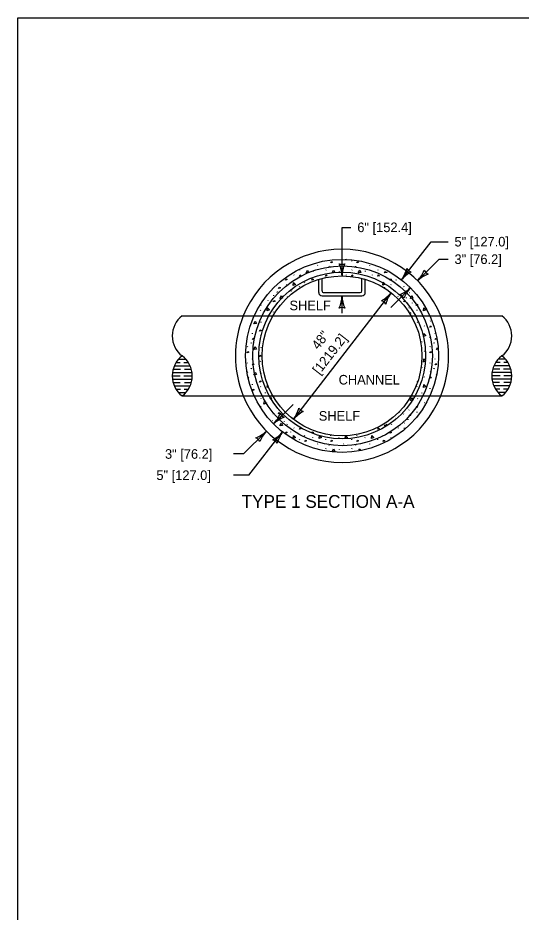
# Model space of a CAD drawing. Extents: x 49991.4 to 50028.3, y 49987.6 to 50011.4.
# Drawn here: x 49999.38 to 50002.53, y 49993.41 to 49999 of the extents above; entities that cross this region are included whole.
import ezdxf

# ---------------------------------------------------------------- set-up
doc = ezdxf.new("R2010")
doc.units = 0
for name, color, linetype in [('Level 1', 7, 'Continuous'), ('Level 2', 7, 'Continuous'), ('Level 3', 7, 'Continuous'), ('Level 4', 7, 'Continuous')]:
    doc.layers.add(name, color=color, linetype=linetype)

msp = doc.modelspace()

# ---------------------------------------------------------------- linework, layer by layer
at = {"layer": 'Level 1'}
for p, q in [((50001.3077, 49997.4809), (50001.308, 49997.4779)), ((50001.471, 49997.4809), (50001.4713, 49997.4779)), ((50001.1475, 49997.422), (50001.1488, 49997.425)), ((50001.2319, 49997.4143), (50001.2332, 49997.4173)), ((50001.2588, 49997.4506), (50001.2602, 49997.4536)), ((50001.3108, 49997.422), (50001.3121, 49997.425)), ((50001.3304, 49997.4467), (50001.3318, 49997.4447)), ((50001.3355, 49997.4459), (50001.3368, 49997.4439)), ((50001.3951, 49997.4143), (50001.3961, 49997.4165)), ((50001.474, 49997.422), (50001.4754, 49997.425)), ((50001.4937, 49997.4467), (50001.495, 49997.4447)), ((50001.4988, 49997.4459), (50001.5001, 49997.4439)), ((50001.5584, 49997.4143), (50001.5597, 49997.4173)), ((50001.5854, 49997.4506), (50001.5867, 49997.4536)), ((50001.6373, 49997.422), (50001.6386, 49997.425)), ((50001.1102, 49997.3931), (50001.1116, 49997.3911)), ((50001.1779, 49997.3434), (50001.1792, 49997.3464)), ((50001.266, 49997.282), (50001.266, 49997.3644)), ((50001.2735, 49997.3931), (50001.2748, 49997.3911)), ((50001.2868, 49997.2924), (50001.2868, 49997.3703)), ((50001.4368, 49997.3931), (50001.4381, 49997.3911)), ((50001.5368, 49997.2924), (50001.5368, 49997.3703)), ((50001.5576, 49997.282), (50001.5576, 49997.3644)), ((50001.6, 49997.3931), (50001.6014, 49997.3911)), ((50001.6677, 49997.3434), (50001.669, 49997.3464)), ((50001.7505, 49997.3597), (50001.7518, 49997.3627)), ((50001.0653, 49997.3298), (50001.0666, 49997.3328)), ((50001.0956, 49997.2911), (50001.0969, 49997.2941)), ((50001.1444, 49997.3214), (50001.1448, 49997.3184)), ((50001.7183, 49997.3298), (50001.7197, 49997.3328)), ((50001.7975, 49997.3214), (50001.7978, 49997.3184)), ((50000.947, 49997.2336), (50000.9483, 49997.2316)), ((50000.9842, 49997.2625), (50000.9856, 49997.2655)), ((50001.0039, 49997.2873), (50001.0052, 49997.2853)), ((50001.009, 49997.2865), (50001.0103, 49997.2845)), ((50001.0686, 49997.2549), (50001.0699, 49997.2579)), ((50001.2868, 49997.2611), (50001.5368, 49997.2611)), ((50001.2972, 49997.282), (50001.5264, 49997.282)), ((50001.7628, 49997.2567), (50001.7637, 49997.2587)), ((50001.8146, 49997.2474), (50001.8159, 49997.2504)), ((50001.835, 49997.2835), (50001.8364, 49997.2815)), ((50001.831, 49997.184), (50001.8323, 49997.187)), ((50001.8501, 49997.2169), (50001.8514, 49997.2149)), ((50000.4118, 49997.1361), (50000.8623, 49997.1361)), ((50000.902, 49997.1703), (50000.9034, 49997.1733)), ((50000.9323, 49997.1317), (50000.9336, 49997.1347)), ((50000.9788, 49997.1361), (50001.8449, 49997.1361)), ((50000.9812, 49997.1619), (50000.9815, 49997.1589)), ((50001.8816, 49997.1703), (50001.8829, 49997.1733)), ((50001.9119, 49997.1317), (50001.9132, 49997.1347)), ((50001.9613, 49997.1361), (50002.4118, 49997.1361)), ((50000.9054, 49997.0955), (50000.9067, 49997.0985)), ((50000.947, 49997.0741), (50000.9483, 49997.0721)), ((50001.8849, 49997.0955), (50001.8863, 49997.0985)), ((50001.9266, 49997.0741), (50001.9279, 49997.0721)), ((50001.9638, 49997.1031), (50001.9652, 49997.1061)), ((50000.8514, 49997.0245), (50000.8527, 49997.0275)), ((50000.902, 49997.0109), (50000.9034, 49997.0139)), ((50001.9942, 49997.0245), (50001.9948, 49997.0257)), ((50000.8406, 49996.9683), (50000.842, 49996.9663)), ((50000.8457, 49996.9676), (50000.847, 49996.9656)), ((50001.9119, 49996.9722), (50001.9132, 49996.9752)), ((50001.9608, 49997.0025), (50001.9611, 49996.9995)), ((50001.9835, 49996.9683), (50001.9848, 49996.9663)), ((50001.9886, 49996.9676), (50001.9899, 49996.9656)), ((50000.821, 49996.9437), (50000.8223, 49996.9467)), ((50000.9054, 49996.936), (50000.9067, 49996.939)), ((50001.9266, 49996.9147), (50001.9279, 49996.9127)), ((50001.9638, 49996.9437), (50001.9652, 49996.9467)), ((50000.3734, 49996.8445), (50000.3995, 49996.8445)), ((50000.3891, 49996.8653), (50000.4345, 49996.8653)), ((50000.4219, 49996.8445), (50000.4502, 49996.8445)), ((50000.8179, 49996.8431), (50000.8182, 49996.8401)), ((50000.8514, 49996.8651), (50000.8527, 49996.8681)), ((50000.902, 49996.8514), (50000.9034, 49996.8544)), ((50001.9608, 49996.8431), (50001.9611, 49996.8401)), ((50001.9942, 49996.8651), (50001.9956, 49996.8681)), ((50002.4017, 49996.8445), (50002.3734, 49996.8445)), ((50002.4346, 49996.8653), (50002.3891, 49996.8653)), ((50002.4502, 49996.8445), (50002.4241, 49996.8445)), ((50000.355, 49996.8028), (50000.4006, 49996.8028)), ((50000.3624, 49996.8236), (50000.4612, 49996.8236)), ((50000.4252, 49996.8028), (50000.4686, 49996.8028)), ((50000.821, 49996.7842), (50000.8223, 49996.7872)), ((50000.8406, 49996.8089), (50000.842, 49996.8069)), ((50000.8457, 49996.8081), (50000.847, 49996.8061)), ((50001.9119, 49996.8128), (50001.9132, 49996.8158)), ((50001.9638, 49996.7842), (50001.9652, 49996.7872)), ((50001.9835, 49996.8089), (50001.9848, 49996.8069)), ((50001.9886, 49996.8081), (50001.9899, 49996.8061)), ((50002.3985, 49996.8028), (50002.355, 49996.8028)), ((50002.4613, 49996.8236), (50002.3624, 49996.8236)), ((50002.4687, 49996.8028), (50002.423, 49996.8028)), ((50000.3493, 49996.7611), (50000.3984, 49996.7611)), ((50000.3507, 49996.7819), (50000.4729, 49996.7819)), ((50000.3507, 49996.7403), (50000.4729, 49996.7403)), ((50000.423, 49996.7611), (50000.4743, 49996.7611)), ((50000.9054, 49996.7765), (50000.9067, 49996.7795)), ((50001.9266, 49996.7552), (50001.9279, 49996.7532)), ((50002.4006, 49996.7611), (50002.3494, 49996.7611)), ((50002.473, 49996.7819), (50002.3508, 49996.7819)), ((50002.473, 49996.7403), (50002.3508, 49996.7403)), ((50002.4744, 49996.7611), (50002.4252, 49996.7611)), ((50000.355, 49996.7195), (50000.3995, 49996.7195)), ((50000.3624, 49996.6986), (50000.4612, 49996.6986)), ((50000.3734, 49996.6778), (50000.4016, 49996.6778)), ((50000.424, 49996.6778), (50000.4502, 49996.6778)), ((50000.4262, 49996.7195), (50000.4686, 49996.7195)), ((50000.8514, 49996.7056), (50000.8527, 49996.7086)), ((50000.902, 49996.6919), (50000.9034, 49996.6949)), ((50001.8816, 49996.6919), (50001.8829, 49996.6949)), ((50001.9608, 49996.6836), (50001.9611, 49996.6806)), ((50002.3974, 49996.7195), (50002.355, 49996.7195)), ((50002.4613, 49996.6986), (50002.3624, 49996.6986)), ((50002.3996, 49996.6778), (50002.3734, 49996.6778)), ((50002.4502, 49996.6778), (50002.422, 49996.6778)), ((50002.4687, 49996.7195), (50002.4241, 49996.7195)), ((50000.3891, 49996.6569), (50000.4345, 49996.6569)), ((50000.4118, 49996.6361), (50000.8624, 49996.6361)), ((50000.9054, 49996.6171), (50000.9067, 49996.6201)), ((50000.9323, 49996.6533), (50000.9336, 49996.6563)), ((50000.9789, 49996.6361), (50001.8448, 49996.6361)), ((50001.8849, 49996.6171), (50001.8863, 49996.6201)), ((50001.9119, 49996.6533), (50001.9132, 49996.6563)), ((50001.9613, 49996.6361), (50002.4118, 49996.6361)), ((50002.4346, 49996.6569), (50002.3891, 49996.6569)), ((50000.947, 49996.5958), (50000.9483, 49996.5938)), ((50001.0092, 49996.5899), (50001.0101, 49996.5886)), ((50001.9266, 49996.5958), (50001.9279, 49996.5938)), ((50000.9812, 49996.5241), (50000.9815, 49996.5211)), ((50001.0146, 49996.5461), (50001.016, 49996.5491)), ((50001.7975, 49996.5241), (50001.7978, 49996.5211)), ((50001.831, 49996.5461), (50001.8323, 49996.5491)), ((50001.8816, 49996.5325), (50001.8829, 49996.5355)), ((50000.9751, 49996.4798), (50000.9765, 49996.4828)), ((50001.0492, 49996.4783), (50001.0505, 49996.4763)), ((50001.0686, 49996.4576), (50001.0699, 49996.4606)), ((50001.0956, 49996.4939), (50001.0962, 49996.4952)), ((50001.7217, 49996.4576), (50001.723, 49996.4606)), ((50001.7486, 49996.4939), (50001.75, 49996.4969)), ((50001.8006, 49996.4653), (50001.8019, 49996.4683)), ((50001.8202, 49996.49), (50001.8216, 49996.488)), ((50001.8253, 49996.4892), (50001.8266, 49996.4872)), ((50001.0892, 49996.4123), (50001.0905, 49996.4103)), ((50001.1102, 49996.4363), (50001.1116, 49996.4343)), ((50001.7633, 49996.4363), (50001.7646, 49996.4343)), ((50001.1444, 49996.3647), (50001.1448, 49996.3617)), ((50001.1779, 49996.3867), (50001.1792, 49996.3897)), ((50001.2286, 49996.3731), (50001.2299, 49996.376)), ((50001.2588, 49996.3344), (50001.2602, 49996.3374)), ((50001.3077, 49996.3647), (50001.308, 49996.3617)), ((50001.3412, 49996.3867), (50001.3425, 49996.3897)), ((50001.3918, 49996.3731), (50001.3932, 49996.376)), ((50001.4221, 49996.3344), (50001.4234, 49996.3374)), ((50001.471, 49996.3647), (50001.4713, 49996.3617)), ((50001.5044, 49996.3867), (50001.5058, 49996.3897)), ((50001.5551, 49996.3731), (50001.5564, 49996.376)), ((50001.5854, 49996.3344), (50001.5867, 49996.3374)), ((50001.6342, 49996.3647), (50001.6346, 49996.3617)), ((50001.6677, 49996.3867), (50001.669, 49996.3897)), ((50001.7183, 49996.3731), (50001.7197, 49996.376)), ((50001.3108, 49996.3058), (50001.3121, 49996.3088)), ((50001.3304, 49996.3305), (50001.3318, 49996.3285)), ((50001.3355, 49996.3297), (50001.3368, 49996.3277)), ((50001.3951, 49996.2982), (50001.3965, 49996.3012)), ((50001.474, 49996.3058), (50001.4754, 49996.3088)), ((50001.4937, 49996.3305), (50001.495, 49996.3285)), ((50001.4988, 49996.3297), (50001.5001, 49996.3277))]:
    msp.add_line(p, q, dxfattribs=at)
msp.add_lwpolyline([(49999.3835, 49998.9992), (50016.7501, 49998.9992), (50016.7501, 49987.7988), (49999.3835, 49987.7988)], close=True, dxfattribs=at)
for points in [[(50001.3418, 49997.4679), (50001.3458, 49997.4763), (50001.3525, 49997.4713), (50001.3418, 49997.4679)], [(50001.4323, 49997.4858), (50001.4328, 49997.4894)], [(50001.4402, 49997.4894), (50001.4326, 49997.4859)], [(50001.5051, 49997.4679), (50001.5091, 49997.4763), (50001.5158, 49997.4713), (50001.5051, 49997.4679)], [(50001.1869, 49997.4054), (50001.1959, 49997.4223), (50001.2029, 49997.4067), (50001.1872, 49997.4054)], [(50001.3502, 49997.4054), (50001.3592, 49997.4223), (50001.3662, 49997.4067), (50001.3505, 49997.4054)], [(50001.5134, 49997.4054), (50001.5224, 49997.4223), (50001.5294, 49997.4067), (50001.5138, 49997.4054)], [(50001.6767, 49997.4054), (50001.6832, 49997.4176)], [(50001.6893, 49997.4143), (50001.6927, 49997.4067), (50001.677, 49997.4054)], [(50001.0587, 49997.3606), (50001.0627, 49997.3689), (50001.0693, 49997.3639), (50001.0587, 49997.3606)], [(50001.1058, 49997.3263), (50001.1084, 49997.3453), (50001.1204, 49997.3331), (50001.1061, 49997.3265)], [(50001.1452, 49997.3844), (50001.1492, 49997.3927), (50001.1558, 49997.3877), (50001.1452, 49997.3844)], [(50001.222, 49997.3606), (50001.226, 49997.3689), (50001.2326, 49997.3639), (50001.222, 49997.3606)], [(50001.3084, 49997.3844), (50001.3124, 49997.3927), (50001.3191, 49997.3877), (50001.3084, 49997.3844)], [(50001.4717, 49997.3844), (50001.4757, 49997.3927), (50001.4824, 49997.3877), (50001.4717, 49997.3844)], [(50001.5517, 49997.3673), (50001.5525, 49997.3689), (50001.558, 49997.3647)], [(50001.635, 49997.3844), (50001.639, 49997.3927), (50001.6456, 49997.3877), (50001.635, 49997.3844)], [(50001.6663, 49997.3288), (50001.669, 49997.3478), (50001.6809, 49997.3355), (50001.6666, 49997.3289)], [(50001.7118, 49997.3606), (50001.7158, 49997.3689), (50001.7224, 49997.3639), (50001.7118, 49997.3606)], [(50001.0153, 49997.3085), (50001.0193, 49997.3168), (50001.026, 49997.3118), (50001.0153, 49997.3085)], [(50001.6714, 49997.3147), (50001.6724, 49997.3168), (50001.679, 49997.3118), (50001.6763, 49997.3109)], [(50001.8316, 49997.3085), (50001.8327, 49997.3107)], [(50001.834, 49997.3092), (50001.8316, 49997.3085)], [(50000.9819, 49997.2249), (50000.9859, 49997.2333), (50000.9926, 49997.2283), (50000.9819, 49997.2249)], [(50001.0236, 49997.2459), (50001.0326, 49997.2629), (50001.0396, 49997.2473), (50001.024, 49997.2459)], [(50001.7982, 49997.2249), (50001.8022, 49997.2333), (50001.8089, 49997.2283), (50001.7982, 49997.2249)], [(50001.84, 49997.2459), (50001.849, 49997.2629), (50001.856, 49997.2473), (50001.8403, 49997.2459)], [(50000.9048, 49997.2054), (50000.9061, 49997.2045), (50000.9039, 49997.2038)], [(50000.9425, 49997.1669), (50000.9452, 49997.1859), (50000.9571, 49997.1736), (50000.9428, 49997.167)], [(50001.875, 49997.2011), (50001.879, 49997.2095), (50001.8857, 49997.2045), (50001.875, 49997.2011)], [(50001.9221, 49997.1669), (50001.9248, 49997.1859), (50001.9361, 49997.1742)], [(50001.8342, 49997.1537), (50001.8356, 49997.1573), (50001.8423, 49997.1523), (50001.8363, 49997.1504)], [(50001.9364, 49997.1735), (50001.9224, 49997.167)], [(50000.8604, 49997.0865), (50000.8694, 49997.1034), (50000.8764, 49997.0878), (50000.8607, 49997.0865)], [(50001.9615, 49997.0655), (50001.9655, 49997.0738), (50001.9722, 49997.0688), (50001.9615, 49997.0655)], [(50000.8954, 49997.0417), (50000.8994, 49997.05), (50000.9061, 49997.045), (50000.8954, 49997.0417)], [(50001.9221, 49997.0074), (50001.9248, 49997.0265), (50001.9367, 49997.0141), (50001.9224, 49997.0075)], [(50000.852, 49996.9895), (50000.856, 49996.9979), (50000.8627, 49996.9929), (50000.852, 49996.9895)], [(50001.9949, 49996.9895), (50001.9989, 49996.9979), (50001.9998, 49996.9973)], [(50002.0008, 49996.9914), (50001.9949, 49996.9895)], [(50000.8187, 49996.906), (50000.8226, 49996.9143), (50000.8293, 49996.9093), (50000.8187, 49996.906)], [(50000.8604, 49996.927), (50000.8694, 49996.944), (50000.8764, 49996.9283), (50000.8607, 49996.927)], [(50001.9615, 49996.906), (50001.9655, 49996.9143), (50001.9722, 49996.9093), (50001.9615, 49996.906)], [(50002.0032, 49996.927), (50002.0099, 49996.9395)], [(50002.0119, 49996.9277), (50002.0036, 49996.927)], [(50000.8954, 49996.8822), (50000.8994, 49996.8905), (50000.9061, 49996.8855), (50000.8954, 49996.8822)], [(50001.9221, 49996.8479), (50001.9248, 49996.867), (50001.9367, 49996.8547), (50001.9224, 49996.8481)], [(50000.852, 49996.8301), (50000.856, 49996.8384), (50000.8627, 49996.8334), (50000.852, 49996.8301)], [(50000.8604, 49996.7675), (50000.8694, 49996.7845), (50000.8764, 49996.7689), (50000.8607, 49996.7675)], [(50001.9949, 49996.8301), (50001.9989, 49996.8384), (50002.0056, 49996.8334), (50001.9949, 49996.8301)], [(50000.8227, 49996.7549), (50000.8293, 49996.7499), (50000.8239, 49996.7482)], [(50000.8954, 49996.7227), (50000.8994, 49996.7311), (50000.9061, 49996.7261), (50000.8954, 49996.7227)], [(50001.8818, 49996.729), (50001.8857, 49996.7261), (50001.88, 49996.7243)], [(50001.9615, 49996.7466), (50001.9655, 49996.7549), (50001.9722, 49996.7499), (50001.9615, 49996.7466)], [(50002.0032, 49996.7675), (50002.0098, 49996.7799)], [(50002.0054, 49996.7677), (50002.0036, 49996.7675)], [(50000.8521, 49996.6708), (50000.856, 49996.679), (50000.8627, 49996.674), (50000.8522, 49996.6707)], [(50000.9425, 49996.6885), (50000.9449, 49996.7059)], [(50000.9494, 49996.6917), (50000.9428, 49996.6886)], [(50001.9221, 49996.6885), (50001.9248, 49996.7075), (50001.9367, 49996.6952), (50001.9224, 49996.6886)], [(50000.9624, 49996.6168), (50000.9664, 49996.6251), (50000.9731, 49996.6201), (50000.9624, 49996.6168)], [(50001.84, 49996.6081), (50001.849, 49996.6251), (50001.856, 49996.6094), (50001.8403, 49996.6081)], [(50000.9002, 49996.5711), (50000.9061, 49996.5666), (50000.9029, 49996.5656)], [(50000.9236, 49996.5843), (50000.9263, 49996.6033), (50000.9382, 49996.591), (50000.924, 49996.5844)], [(50001.875, 49996.5633), (50001.879, 49996.5716), (50001.8857, 49996.5666), (50001.875, 49996.5633)], [(50001.0135, 49996.5233), (50001.0175, 49996.5316), (50001.0242, 49996.5266), (50001.0135, 49996.5233)], [(50001.7713, 49996.538), (50001.7734, 49996.5358), (50001.7672, 49996.5329)], [(50001.8316, 49996.5112), (50001.8356, 49996.5195), (50001.8423, 49996.5145), (50001.8316, 49996.5112)], [(50001.0236, 49996.4486), (50001.0326, 49996.4656), (50001.0396, 49996.45), (50001.024, 49996.4486)], [(50001.6767, 49996.4486), (50001.6811, 49996.457)], [(50001.6876, 49996.4615), (50001.6927, 49996.45), (50001.677, 49996.4486)], [(50001.0587, 49996.4039), (50001.0627, 49996.4122), (50001.0693, 49996.4072), (50001.0587, 49996.4039)], [(50001.1452, 49996.4277), (50001.1492, 49996.436), (50001.1558, 49996.431), (50001.1452, 49996.4277)], [(50001.222, 49996.4039), (50001.226, 49996.4122), (50001.2326, 49996.4072), (50001.222, 49996.4039)], [(50001.635, 49996.4277), (50001.639, 49996.436), (50001.6456, 49996.431), (50001.635, 49996.4277)], [(50001.7118, 49996.4039), (50001.7158, 49996.4122), (50001.7224, 49996.4072), (50001.7118, 49996.4039)], [(50001.801, 49996.4333), (50001.8022, 49996.436), (50001.8032, 49996.4353)], [(50001.1058, 49996.3696), (50001.1084, 49996.3886), (50001.1204, 49996.3763), (50001.1061, 49996.3697)], [(50001.1786, 49996.3517), (50001.1826, 49996.3601), (50001.1892, 49996.3551), (50001.1786, 49996.3517)], [(50001.269, 49996.3696), (50001.2717, 49996.3886), (50001.2836, 49996.3763), (50001.2694, 49996.3697)], [(50001.3418, 49996.3517), (50001.3458, 49996.3601), (50001.3525, 49996.3551), (50001.3418, 49996.3517)], [(50001.4323, 49996.3696), (50001.4344, 49996.3847)], [(50001.4382, 49996.3853), (50001.4469, 49996.3763), (50001.4326, 49996.3697)], [(50001.5051, 49996.3517), (50001.5091, 49996.3601), (50001.5158, 49996.3551), (50001.5051, 49996.3517)], [(50001.5956, 49996.3696), (50001.5982, 49996.3886), (50001.6102, 49996.3763), (50001.5959, 49996.3697)], [(50001.6684, 49996.3517), (50001.6724, 49996.3601), (50001.679, 49996.3551), (50001.6684, 49996.3517)], [(50001.3504, 49996.2895), (50001.3592, 49996.3061), (50001.3662, 49996.2905), (50001.3537, 49996.2895)], [(50001.3536, 49996.2895), (50001.3535, 49996.2895)], [(50001.3535, 49996.2895), (50001.3535, 49996.2895)], [(50001.3537, 49996.2895), (50001.3536, 49996.2895)], [(50001.3536, 49996.2895), (50001.3536, 49996.2895)], [(50001.5171, 49996.2961), (50001.5224, 49996.3061), (50001.526, 49996.2981)]]:
    msp.add_lwpolyline(points, dxfattribs=at)
for centre, radius in [((50001.4119, 49996.8861), 0.6037), ((50001.4152, 49996.8868), 0.5619), ((50001.4128, 49996.8893), 0.5213), ((50001.4119, 49996.8861), 0.5)]:
    msp.add_circle(centre, radius, dxfattribs=at)
for centre, radius, start, end in [((50001.4118, 49996.8864), 0.6664, 22.0028, 157.9972), ((50000.5056, 49997.0111), 0.1563, 126.8699, 233.1301), ((50002.3181, 49997.0111), 0.1563, 306.8699, 53.1301), ((50000.5056, 49996.7611), 0.1563, 126.8699, 233.1301), ((50000.3181, 49996.7611), 0.1563, 306.8699, 53.1301), ((50002.5056, 49996.7611), 0.1563, 126.8699, 233.1301), ((50002.3181, 49996.7611), 0.1563, 306.8699, 53.1301), ((50001.4118, 49996.886), 0.6665, 202.0199, 337.9801)]:
    msp.add_arc(centre, radius, start, end, dxfattribs=at)
for centre, major_axis, start_param, end_param in [((50001.2973, 49997.2924), (0, 0.0104), 1.570796, 3.141593), ((50001.5264, 49997.2924), (0, -0.0104), 0, 1.570796), ((50001.2869, 49997.282), (0, 0.0208), 1.570796, 3.141593), ((50001.5368, 49997.282), (0, -0.0208), 0, 1.570796)]:
    msp.add_ellipse(centre, major_axis=major_axis, ratio=0.99996, start_param=start_param, end_param=end_param, dxfattribs=at)
at = {"layer": 'Level 3'}
for p, q in [((50001.4118, 49997.6898), (50001.4677, 49997.6898)), ((50001.4118, 49997.3861), (50001.4118, 49997.6898)), ((50001.7839, 49997.3616), (50001.9704, 49997.6002)), ((50001.9704, 49997.6002), (50002.0756, 49997.6002)), ((50001.8846, 49997.3561), (50002.0197, 49997.4906)), ((50002.0197, 49997.4906), (50002.0756, 49997.4906)), ((50001.717, 49997.1896), (50001.84, 49997.3117)), ((50001.1079, 49996.4891), (50001.7189, 49997.2807)), ((50001.4118, 49997.154), (50001.4118, 49997.2611)), ((50000.9837, 49996.4605), (50001.1068, 49996.5827)), ((50000.9837, 49996.4605), (50001.0453, 49996.5218)), ((50000.7951, 49996.273), (50000.9369, 49996.4139)), ((50000.8284, 49996.1402), (50001.0399, 49996.4106)), ((50000.7951, 49996.273), (50000.7329, 49996.273)), ((50000.8284, 49996.1402), (50000.7329, 49996.1402))]:
    msp.add_line(p, q, dxfattribs=at)
for centre, radius, start, end in [((50001.4118, 49997.5143), 0.0548, 252.1388, 287.8612), ((50001.1791, 49997.3746), 0.233, 2.8273, 22.0772), ((50001.634, 49997.377), 0.2223, 157.456, 177.6395), ((50001.5935, 49997.4959), 0.233, 324.7992, 344.049), ((50001.9532, 49997.2175), 0.2223, 119.4279, 139.6114), ((50001.8628, 49997.4626), 0.0548, 214.1107, 249.8331), ((50001.7123, 49997.5129), 0.233, 317.6876, 336.9375), ((50001.9755, 49997.4465), 0.0548, 206.9991, 242.7215), ((50002.0348, 49997.1922), 0.2223, 112.3163, 132.4998), ((50001.6899, 49997.4758), 0.2223, 292.2764, 312.4599), ((50002.0122, 49997.1548), 0.233, 137.6477, 156.8976), ((50001.1897, 49997.2702), 0.2223, 337.456, 357.6395), ((50001.6446, 49997.2726), 0.233, 182.8273, 202.0772), ((50001.5496, 49997.4248), 0.2223, 299.4184, 319.6019), ((50001.9093, 49997.1464), 0.233, 144.7897, 164.0396), ((50001.7491, 49997.2214), 0.0548, 26.9592, 62.6816), ((50001.4118, 49997.1329), 0.0548, 72.1388, 107.8612), ((50001.6399, 49997.1797), 0.0548, 34.1012, 69.8236), ((50000.8114, 49996.6173), 0.233, 317.6875, 336.9373), ((50001.0746, 49996.5509), 0.0548, 206.999, 242.7213), ((50000.9175, 49996.6234), 0.233, 324.806, 344.0558), ((50001.2773, 49996.3451), 0.2223, 119.4347, 139.6182), ((50001.1869, 49996.5901), 0.0548, 214.1175, 249.8398), ((50001.1339, 49996.2966), 0.2223, 112.3162, 132.4997), ((50000.7891, 49996.5801), 0.2223, 292.2764, 312.4599), ((50001.1113, 49996.2591), 0.233, 137.6477, 156.8976), ((50000.8706, 49996.5547), 0.2223, 299.4143, 319.5978), ((50001.2303, 49996.2762), 0.233, 144.7856, 164.0354), ((50000.8482, 49996.3257), 0.0548, 26.9592, 62.6816), ((50000.9609, 49996.3096), 0.0548, 34.0971, 69.8194)]:
    msp.add_arc(centre, radius, start, end, dxfattribs=at)
at = {"layer": 'Level 4'}
for p, q in [((50000.8623, 49997.1361), (50000.9788, 49997.1361)), ((50001.8449, 49997.1361), (50001.9613, 49997.1361)), ((50000.8624, 49996.6361), (50000.9789, 49996.6361)), ((50001.8448, 49996.6361), (50001.9613, 49996.6361))]:
    msp.add_line(p, q, dxfattribs=at)
for start, end in [(157.9719, 202.0281), (337.9719, 22.0281)]:
    msp.add_arc((50001.4118, 49996.8861), 0.6666, start, end, dxfattribs=at)

# ---------------------------------------------------------------- texts
at = {"layer": 'Level 2'}
for s, height, p in [('6" [152.4]', 0.06, (50001.5077, 49997.6598)), ('5" [127.0]', 0.06, (50002.1156, 49997.5702)), ('3" [76.2]', 0.06, (50002.1156, 49997.4606)), ('SHELF', 0.06, (50001.0831, 49997.1716)), ('CHANNEL', 0.06, (50001.3907, 49996.7072)), ('SHELF', 0.06, (50001.2664, 49996.4811)), ('3" [76.2]', 0.06, (50000.3043, 49996.243)), ('5" [127.0]', 0.06, (50000.2505, 49996.1102)), ('TYPE 1 SECTION A-A', 0.08, (50000.7839, 49995.9363))]:
    msp.add_text(s, height=height, dxfattribs=at).set_placement(p)
for s, p in [('[1219.2]', (50001.2697, 49996.765)), ('48"', (50001.2635, 49996.9201))]:
    msp.add_text(s, height=0.06, rotation=52.166, dxfattribs=at).set_placement(p)

doc.saveas('drawing.dxf')
